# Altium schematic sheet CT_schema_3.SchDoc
size 283 x 147 mm
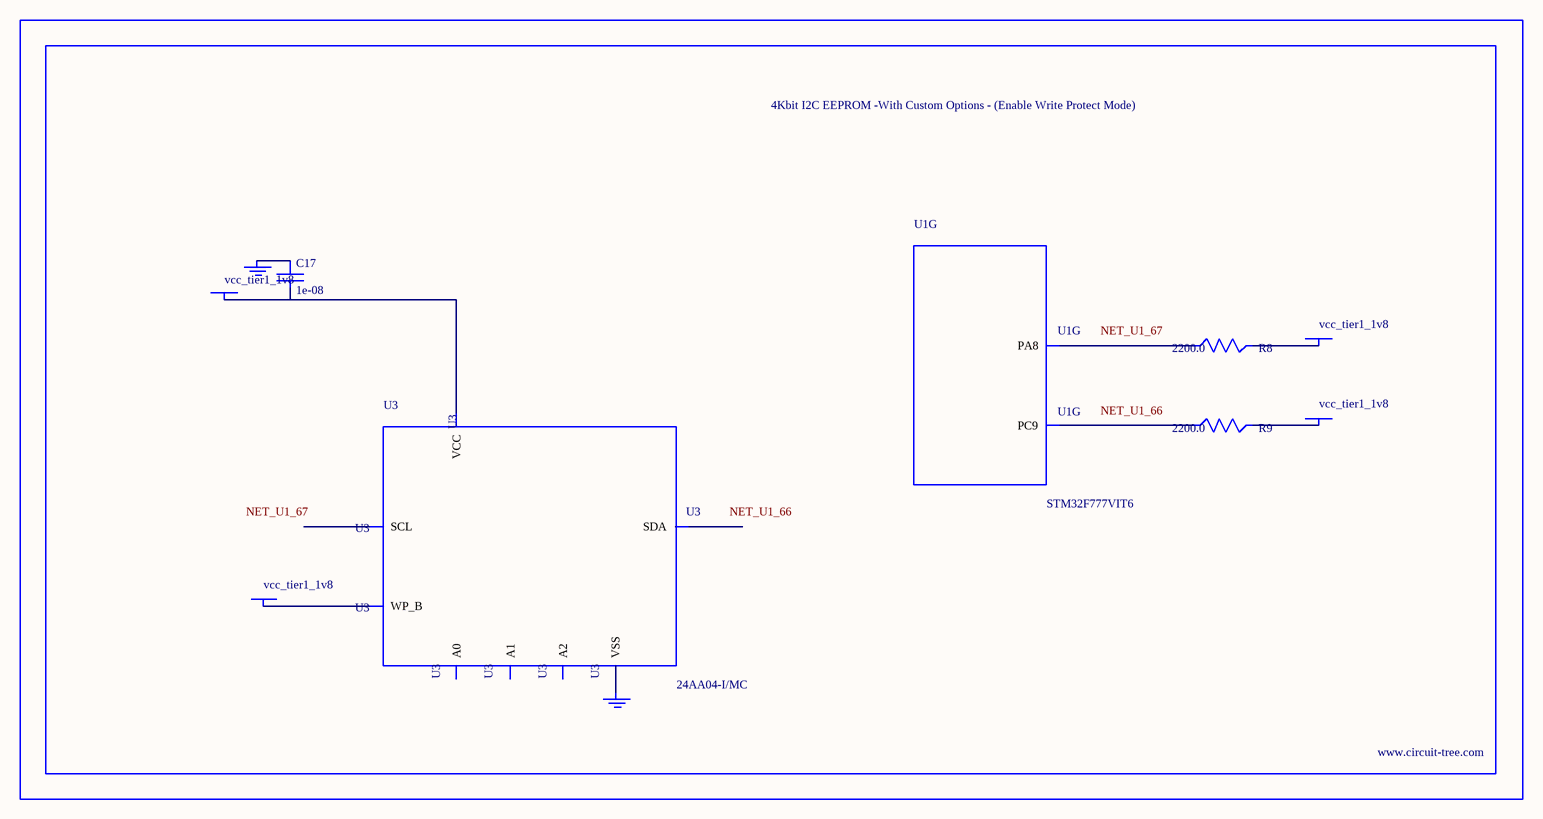
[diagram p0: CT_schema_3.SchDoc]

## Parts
BORDER2  (no value)
C17  1e-08  [C0402]
GND_INSTANCE_2_0  (no value)
GND_INSTANCE_2_1  (no value)
POWER_INSTANCE_2_0  vcc_tier1_1v8
POWER_INSTANCE_2_1  vcc_tier1_1v8
POWER_INSTANCE_2_2  vcc_tier1_1v8
POWER_INSTANCE_2_3  vcc_tier1_1v8
R8  2200.0  [R0603]
R9  2200.0  [R0603]
U1  STM32F777VIT6  [LQFP100]  (part G of 11)
U3  24AA04-I/MC  [TDFN-8/6MM]

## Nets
NetC17_1: C17.1 GND_INSTANCE_2_0.0(GND)
NetC17_2: C17.2 POWER_INSTANCE_2_1.0(PWR) U3.8(VCC)
NetGND_INSTANCE_2_1_0: GND_INSTANCE_2_1.0(GND) U3.4(VSS)
NetPOWER_INSTANCE_2_0_0: POWER_INSTANCE_2_0.0(PWR) U3.7(WP_B)
NetPOWER_INSTANCE_2_2_0: POWER_INSTANCE_2_2.0(PWR) R9.2
NetPOWER_INSTANCE_2_3_0: POWER_INSTANCE_2_3.0(PWR) R8.2
NetR8_1: R8.1 U1.67(PA8)
NetR9_1: R9.1 U1.66(PC9)

Not connected (* = marked no-connect by the designer): U3 1(A0) 2(A1) 3(A2) 5(SDA) 6(SCL)

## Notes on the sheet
- Labels drawn without touching a wire or pin: NET_U1_66, NET_U1_67

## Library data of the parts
BORDER2 = BORDER_PAGE2
C17 = C0402C103K3RAC
GND_INSTANCE_2_0 GND_INSTANCE_2_1 = GND
POWER_INSTANCE_2_0-POWER_INSTANCE_2_3 = PWR
R8 R9 = RC0603JR-072K2L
